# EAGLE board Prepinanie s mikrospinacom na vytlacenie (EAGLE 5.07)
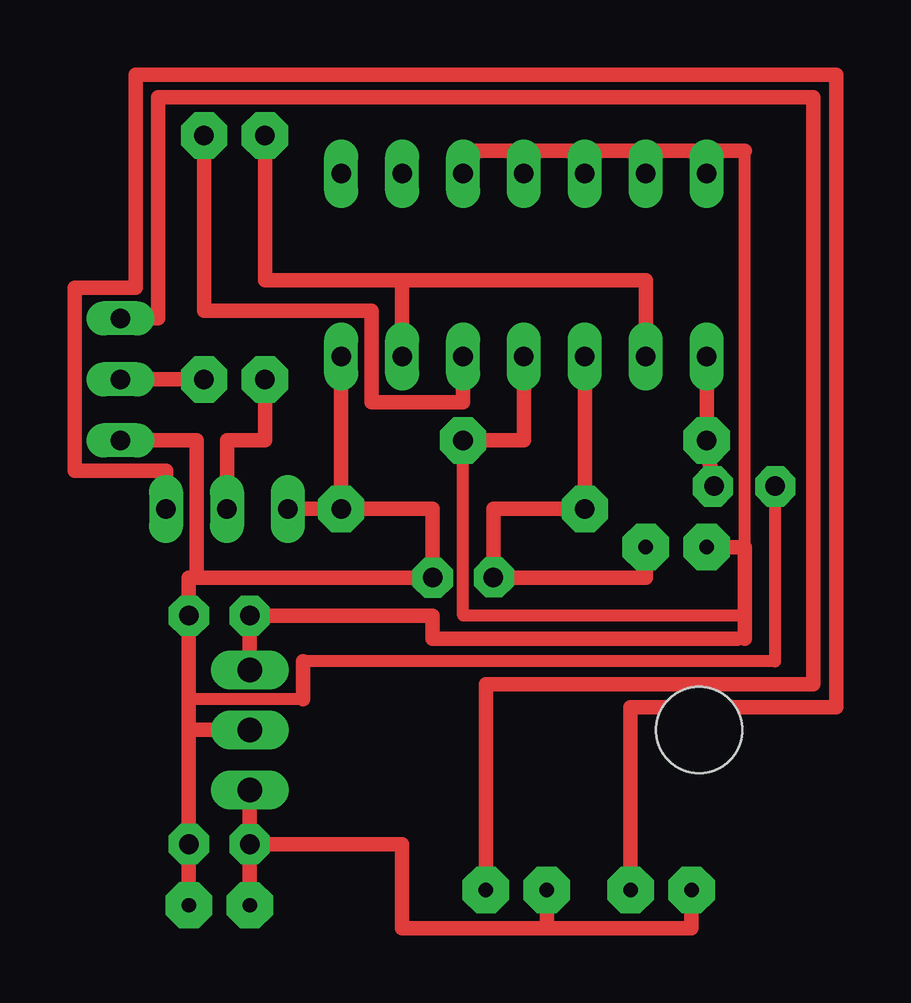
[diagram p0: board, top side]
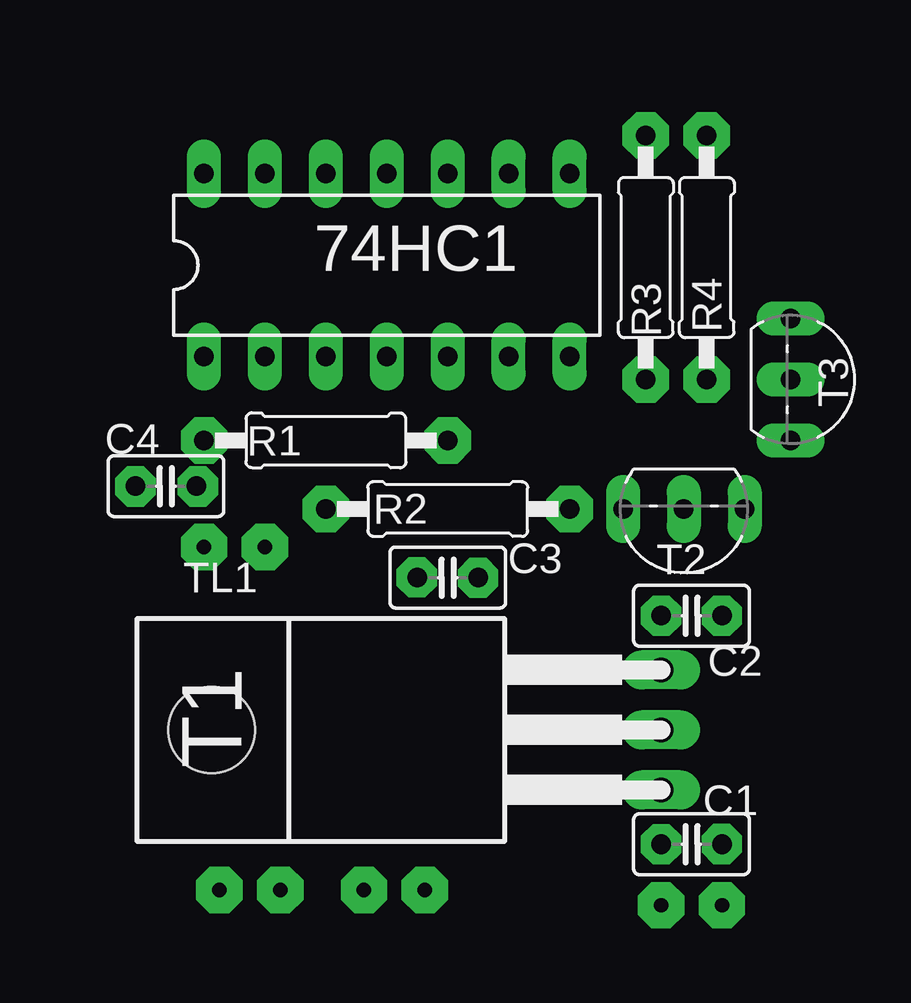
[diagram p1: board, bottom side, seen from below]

No outline drawn. Coordinates in mm, seen from the top.
Copper layers (1*16): Top 0.035mm / dielectric 1.5mm / Bottom 0.035mm
Design rules "default *": minimum track width 10mil, minimum drill 24mil, track to track 8mil, track to pad 8mil, pad to pad 8mil, via to via 8mil, smd to smd 8mil, copper to edge 40mil, drill to drill 8mil, minimum pad ring 12mil, minimum via ring 8mil, stop-mask expansion 4mil, vias tented up to drill 0mil, thermal gap 10mil

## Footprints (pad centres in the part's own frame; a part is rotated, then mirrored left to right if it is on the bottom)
DIL14 = drill 0.813 long: 1 -7.62,-3.81; 2 -5.08,-3.81; 3 -2.54,-3.81; 4 0,-3.81; 5 2.54,-3.81; 6 5.08,-3.81; 7 7.62,-3.81; 8 7.62,3.81; 9 5.08,3.81; 10 2.54,3.81; 11 0,3.81; 12 -2.54,3.81; 13 -5.08,3.81; 14 -7.62,3.81
C025-025X050 = drill 0.813 octagon: 1 -1.27,0; 2 1.27,0
R-10 = drill 0.813 pad 1.93 octagon: 1 -5.08,0; 2 5.08,0
T-30 = drill 1.016 long: 1 -2.5,-18.735; 2 0,-18.735; 3 2.5,-18.735 | hole 3.6: 0,0
TO92-CBE = drill 0.813 long: B 0,0; C -2.54,0; E 2.54,0

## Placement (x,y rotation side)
74HC1  [DIL14]  51.75,38.1 0 bottom
C1  [C025-025X050]  39.05,13.97 0 bottom
C2  [C025-025X050]  39.05,23.5 0 bottom
C3  [C025-025X050]  49.21,25.08 180 bottom
C4  [C025-025X050]  60.96,28.89 180 bottom
R1  [R-10]  54.29,30.8 180 bottom
R2  [R-10]  49.21,27.94 0 bottom
R3  [R-10]  40.96,38.42 270 bottom
R4  [R-10]  38.42,38.42 270 bottom
T1  [T-30]  59.05,18.73 90 bottom
T2  [TO92-CBE]  39.37,27.94 180 bottom
T3  [TO92-CBE]  34.92,33.34 270 bottom

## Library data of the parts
74HC1 = 74ac-logic
C1-C4 = rcl
R1-R4 = #PaJa_21
T1-T3 = transistor

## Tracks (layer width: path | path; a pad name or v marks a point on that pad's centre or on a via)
S$2
  Top 0.61: 35.88,30.8 38.1,30.8 38.1,25.08 | 37.78,24.13 37.78,25.08 38.1,25.08 | 47.31,25.08 38.1,25.08
S$3
  Top 0.61: 40.32,12.38 40.32,13.34
S$5  (via drill 0.6 pad 1.68)
  other vias: 38.43,43.51
S$6  (via drill 0.6 pad 1.68)
  other vias: 59.63,28.88
S$7  (via drill 0.6 pad 1.68)
  other vias: 54.3,27.95
S$8  (via drill 0.6 pad 1.68)
  other vias: 47.95,25.07
S$9  (via drill 0.6 pad 1.68)
  other vias: 49.21,30.81
S$11  (via drill 0.6 pad 1.68)
  other vias: 59.39,30.81
S$12  (via drill 0.6 pad 1.68)
  other vias: 62.23,28.88
S$13  (via drill 0.6 pad 1.68)
  other vias: 37.79,23.49
S$14  (via drill 0.6 pad 1.68)
  other vias: 44.15,27.94
S$15  (via drill 0.6 pad 1.68)
  other vias: 37.79,13.98
S$16
  Top 0.61: 37.78,13.34 37.78,12.06
S$17  (via drill 0.6 pad 1.68)
  other vias: 40.32,23.49
S$18  (via drill 0.6 pad 1.68)
  other vias: 40.32,13.97
S$19  (via drill 0.6 pad 1.68)
  other vias: 40.97,33.32
S$20  (via drill 0.6 pad 1.68)
  other vias: 38.42,33.33
S$21  (via drill 0.6 pad 1.68)
  other vias: 40.96,43.51
S$22  (via drill 0.6 pad 1.68)
  other vias: 50.5,25.09
S$55  (via drill 0.6 pad 1.93)
  other vias: 59.37,26.35
S$56  (via drill 0.6 pad 1.93)
  other vias: 50.16,12.06
S$57  (via drill 0.6 pad 1.93)
  other vias: 56.2,12.06
S$60  (via drill 0.6 pad 1.93)
  other vias: 56.83,26.35
S$61  (via drill 0.6 pad 1.93)
  other vias: 52.7,12.06 40.32,11.43 37.78,11.43 58.74,12.06
S$62
  Top 0.61: 59.37,33.02 59.37,31.43
S$63
  Top 0.61: 49.85,30.8 51.75,30.8 51.75,33.02
S$64
  Top 0.61: 54.29,33.02 54.29,28.57
S$65
  Top 0.61: 44.13,33.02 44.13,28.57
S$66
  Top 0.61: 44.77,27.94 47.94,27.94 47.94,25.72
S$67
  Top 0.61: 53.66,27.94 50.48,27.94 50.48,25.72
S$68
  Top 0.61: 51.12,25.08 56.83,25.08 56.83,25.4
S$69
  Top 0.61: 40.32,14.61 40.32,15.56
S$70
  Top 0.5: 49.21,30.16 49.21,23.5 60.96,23.5 | 60.96,26.35 60.96,42.86
  Top 0.61: 60.96,42.86 49.21,42.86 | 60.01,26.35 60.96,26.35 60.96,23.5 60.96,22.54
S$71
  Top 0.61: 59.37,30.16 59.59,29.56
S$72
  Top 0.5: 42.55,20 37.78,20 | 42.55,21.59 62.23,21.59 62.23,28.26
  Top 0.61: 37.78,18.73 37.78,14.61 | 37.78,18.73 39.05,18.73 | 37.78,18.73 37.78,20 37.78,22.86 | 42.55,21.59 42.55,20
S$73
  Top 0.61: 40.32,21.91 40.32,22.86
S$74
  Top 0.61: 60.64,22.54 47.94,22.54 47.94,23.5 40.96,23.5
S$76
  Top 0.61: 40.96,13.97 46.67,13.97 46.67,12.7
S$77
  Top 0.61: 46.67,12.7 46.67,10.48 52.7,10.48 | 52.7,10.48 52.7,11.11 | 52.7,10.48 58.74,10.48 58.74,11.11
S$78
  Top 0.61: 40.96,42.86 40.96,37.47 46.67,37.47 | 56.83,35.56 56.83,37.47 46.67,37.47 | 46.67,37.47 46.67,35.56
S$79
  Top 0.61: 38.42,42.86 38.42,36.2 45.4,36.2 45.4,32.38 49.21,32.38 49.21,33.02
S$80
  Top 0.61: 43.5,27.94 42.55,27.94
S$81
  Top 0.61: 40.96,32.7 40.96,30.8 39.37,30.8 39.37,28.89
S$82
  Top 0.61: 35.88,33.34 37.78,33.34
S$84
  Top 0.61: 50.16,12.7 50.16,20.64 63.82,20.64 63.82,45.09 36.51,45.09 36.51,35.88 35.88,35.88
S$85
  Top 0.61: 36.83,29.21 36.83,29.53 33.02,29.53 33.02,37.15 35.56,37.15 35.56,46.04 64.77,46.04 64.77,19.68 56.2,19.68 56.2,12.7

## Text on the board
bNames: TL1
Document: Prepinanie 2 LED s mikrospinacom | FoXo 2010 | - LED2 | - LED1 | + | + | +12V | 0 V
Doplnky: E | B | C | C | B | E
